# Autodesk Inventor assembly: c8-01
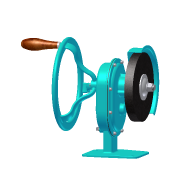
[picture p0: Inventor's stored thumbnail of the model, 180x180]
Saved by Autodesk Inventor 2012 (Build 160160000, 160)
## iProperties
Created: 2010-12
Part Number: c8-01
Document SubType Name: Assembly
Designer: Thom Tremblay
Author: Thom Tremblay
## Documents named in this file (27)
- C:\Users\VMuser\Desktop\Inventor 2012 Essentials\Assemblies\Chapter 8\c8-01.iam
- C:\Users\VMuser\Desktop\Inventor 2012 Essentials\Content Center Files\en-US\ANSI B93.98M\ANSI_B93.98M - 15x35x7-Type 2.ipt
- C:\Users\VMuser\Desktop\Inventor 2012 Essentials\Content Center Files\en-US\SKF B - angular contact\SKF B7202 BE.ipt
- C:\Users\VMuser\Desktop\Inventor 2012 Essentials\Content Center Files\en-US\IS 7483\IS 7483 - M4 x 8.ipt
- C:\Users\VMuser\Desktop\Inventor 2012 Essentials\Content Center Files\en-US\ISO 2795  F\ISO 2795 - 10 x 14 x 10F.ipt
- C:\Users\VMuser\Desktop\Inventor 2012 Essentials\Content Center Files\en-US\STN 022930\STN 022930 - 10.ipt
- C:\Users\VMuser\Desktop\Inventor 2012 Essentials\Content Center Files\en-US\STN 022930\STN 022930 - 15.ipt
- C:\Users\VMuser\Desktop\Inventor 2012 Essentials\Content Center Files\en-US\DIN 128\DIN 128 - A12.ipt
- C:\Users\VMuser\Desktop\Inventor 2012 Essentials\Content Center Files\en-US\ISO 4032\ISO 4032 - M12ISO.ipt
- C:\Users\VMuser\Desktop\Inventor 2012 Essentials\Content Center Files\en-US\ISO 4145 T8\ISO 4145 Plug T8 1_8.ipt
- C:\Users\VMuser\Desktop\Inventor 2012 Essentials\Parts\Chapter 8\c8-01.ipt
- C:\Users\VMuser\Desktop\Inventor 2012 Essentials\Parts\Chapter 8\c8-02.ipt
- C:\Users\VMuser\Desktop\Inventor 2012 Essentials\Parts\Chapter 8\c8-03.ipt
- C:\Users\VMuser\Desktop\Inventor 2012 Essentials\Parts\Chapter 8\c8-04.ipt
- C:\Users\VMuser\Desktop\Inventor 2012 Essentials\Parts\Chapter 8\c8-05.ipt
- C:\Users\VMuser\Desktop\Inventor 2012 Essentials\Parts\Chapter 8\c8-08.ipt
- C:\Users\VMuser\Desktop\Inventor 2012 Essentials\Parts\Chapter 8\c8-06.ipt
- C:\Users\VMuser\Desktop\Inventor 2012 Essentials\Parts\Chapter 8\c8-07.ipt
- C:\Users\VMuser\Desktop\Inventor 2012 Essentials\Assemblies\Chapter 8\Design Accelerators\Shaft c8-01.iam
- C:\Users\VMuser\Desktop\Inventor 2012 Essentials\Assemblies\Chapter 8\Design Accelerators\Shaft c8-02.iam
- C:\Users\VMuser\Desktop\Inventor 2012 Essentials\Assemblies\Chapter 8\Design Accelerators\Shaft c8-03.iam
- C:\Users\VMuser\Desktop\Inventor 2012 Essentials\Assemblies\Chapter 8\Design Accelerators\Cut Gear c08-01.iam
- C:\Users\VMuser\Desktop\Inventor 2012 Essentials\Assemblies\Chapter 8\Design Accelerators\Cut Gear c08-02.iam
- C:\Users\VMuser\Desktop\Inventor 2012 Essentials\Assemblies\Chapter 8\Design Accelerators\Spur Gear c98-01.iam
- C:\Users\VMuser\Desktop\Inventor 2012 Essentials\Assemblies\Chapter 8\Design Accelerators\Key Connection c8-01.iam
- C:\Users\VMuser\Desktop\Inventor 2012 Essentials\Assemblies\Chapter 8\Design Accelerators\Bolted Connection c8-01.iam
- C:\Users\VMuser\Desktop\Inventor 2012 Essentials\Assemblies\Chapter 8\Design Accelerators\Bolted Connection c8-02.iam
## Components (31 placed, 24 different names)
1. c8-01:1 — Insert:1, Flush:3, Insert:27, Insert:28, Insert:39, Angle:19
2. c8-02:1 — Insert:1, Insert:17, Insert:18, Insert:25, Insert:26, Insert:40, Angle:19, Mate:18, Mate:19
3. ANSI/B93.98M 15x35x7-Type 2:1 — Insert:40
4. c8-03:1 — Flush:3
5. c8-04:1 — Insert:10, Angle:17, Insert:49, Mate:16, Angle:20
6. c8-05:1 — Insert:10
7. c8-08:1 — Insert:13, Insert:16, Insert:48
8. c8-08:2 — Insert:13
9. c8-06:1 — Insert:16, Angle:11
10. c8-07:1 — Insert:17, Insert:18
11. SKF B- Angular contact SKF B7202 BE:1 — Insert:25, Insert:45
12. IS 7483 M4 x 8:1
13. IS 7483 M4 x 8:2
14. ISO 2795 (Flanged) 10 x 14 x 10:1 — Insert:26
15. ISO 2795 (Flanged) 10 x 14 x 10:2 — Insert:27, Insert:46
16. ISO 2795 (Flanged) 10 x 14 x 10:3 — Insert:28, Insert:41
17. STN 022930 10:1 — Angle:16
18. STN 022930 15:1
19. STN 022930 15:2
20. DIN 128 A12:1 — Angle:10
21. ISO 4032 M12:1 — Angle:10, Angle:11, Angle:18
22. ISO 4145 Plug T8 1/8:1 — Insert:39
23. Input Shaft [sub-assembly] — Insert:41, Angle:16, Angle:17, Insert:49, Mate:17, Rotation:1, Rotation:2
24. Output Shaft:2 [sub-assembly] — Insert:45, Flush:4, Insert:48, Angle:18, Rotation:2
25. Transfer Shaft:1 [sub-assembly] — Insert:46, Mate:12, Flush:5, Angle:14, Mate:13, Angle:15, Rotation:1, Rotation:3
26. Cut Gear:1 [sub-assembly]
27. Cut Gear:2 [sub-assembly]
28. Cut Gear:3 [sub-assembly] — Mate:12, Flush:4, Angle:15, Rotation:3
29. Key Connection:1 [sub-assembly] — Flush:5, Angle:14, Mate:13
30. Housing Bolts:1 [sub-assembly] — Mate:18, Mate:19
31. Wheel Bolt [sub-assembly] — Mate:16, Mate:17, Angle:20
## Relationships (38: Insert 17, Angle 9, Mate 6, Flush 3, RelateRotation 3)
- Insert:1: c8-01:1 ↔ c8-02:1
- Flush:3: c8-01:1 ↔ c8-03:1
- Insert:10: c8-04:1 ↔ c8-05:1
- Insert:13: c8-08:1 ↔ c8-08:2
- Insert:16: c8-08:1 ↔ c8-06:1
- Insert:17: c8-02:1 ↔ c8-07:1
- Insert:18: c8-02:1 ↔ c8-07:1
- Insert:25: c8-02:1 ↔ SKF B- Angular contact SKF B7202 BE:1
- Insert:26: c8-02:1 ↔ ISO 2795 (Flanged) 10 x 14 x 10:1
- Insert:27: c8-01:1 ↔ ISO 2795 (Flanged) 10 x 14 x 10:2
- Insert:28: c8-01:1 ↔ ISO 2795 (Flanged) 10 x 14 x 10:3
- Angle:10: DIN 128 A12:1 ↔ ISO 4032 M12:1
- Angle:11: c8-06:1 ↔ ISO 4032 M12:1
- Insert:39: c8-01:1 ↔ ISO 4145 Plug T8 1/8:1
- Insert:40: c8-02:1 ↔ ANSI/B93.98M 15x35x7-Type 2:1
- Insert:41: ISO 2795 (Flanged) 10 x 14 x 10:3 ↔ Input Shaft
- Insert:45: SKF B- Angular contact SKF B7202 BE:1 ↔ Output Shaft:2
- Insert:46: ISO 2795 (Flanged) 10 x 14 x 10:2 ↔ Transfer Shaft:1
- Mate:12: Transfer Shaft:1 ↔ Cut Gear:3
- Flush:4: Output Shaft:2 ↔ Cut Gear:3
- Flush:5: Transfer Shaft:1 ↔ Key Connection:1
- Angle:14: Transfer Shaft:1 ↔ Key Connection:1
- Mate:13: Transfer Shaft:1 ↔ Key Connection:1
- Angle:15: Transfer Shaft:1 ↔ Cut Gear:3
- Angle:16: STN 022930 10:1 ↔ Input Shaft
- Angle:17: c8-04:1 ↔ Input Shaft
- Insert:48: c8-08:1 ↔ Output Shaft:2
- Angle:18: ISO 4032 M12:1 ↔ Output Shaft:2
- Insert:49: c8-04:1 ↔ Input Shaft
- Mate:16: c8-04:1 ↔ Wheel Bolt
- Mate:17: Input Shaft ↔ Wheel Bolt
- Angle:19: c8-01:1 ↔ c8-02:1
- Rotation:1 [RelateRotation]: Input Shaft ↔ Transfer Shaft:1
- Rotation:2 [RelateRotation]: Input Shaft ↔ Output Shaft:2
- Rotation:3 [RelateRotation]: Transfer Shaft:1 ↔ Cut Gear:3
- Mate:18: c8-02:1 ↔ Housing Bolts:1
- Mate:19: c8-02:1 ↔ Housing Bolts:1
- Angle:20: c8-04:1 ↔ Wheel Bolt
